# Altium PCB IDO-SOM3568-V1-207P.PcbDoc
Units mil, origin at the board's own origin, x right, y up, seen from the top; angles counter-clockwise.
Board outline 3000 x 2000 mil, 4 copper layers (TOP, VCC, GND, BOTTOM), stack 28.8 mil thick; 1 components, 686 nets, 207 pads, 0 vias.
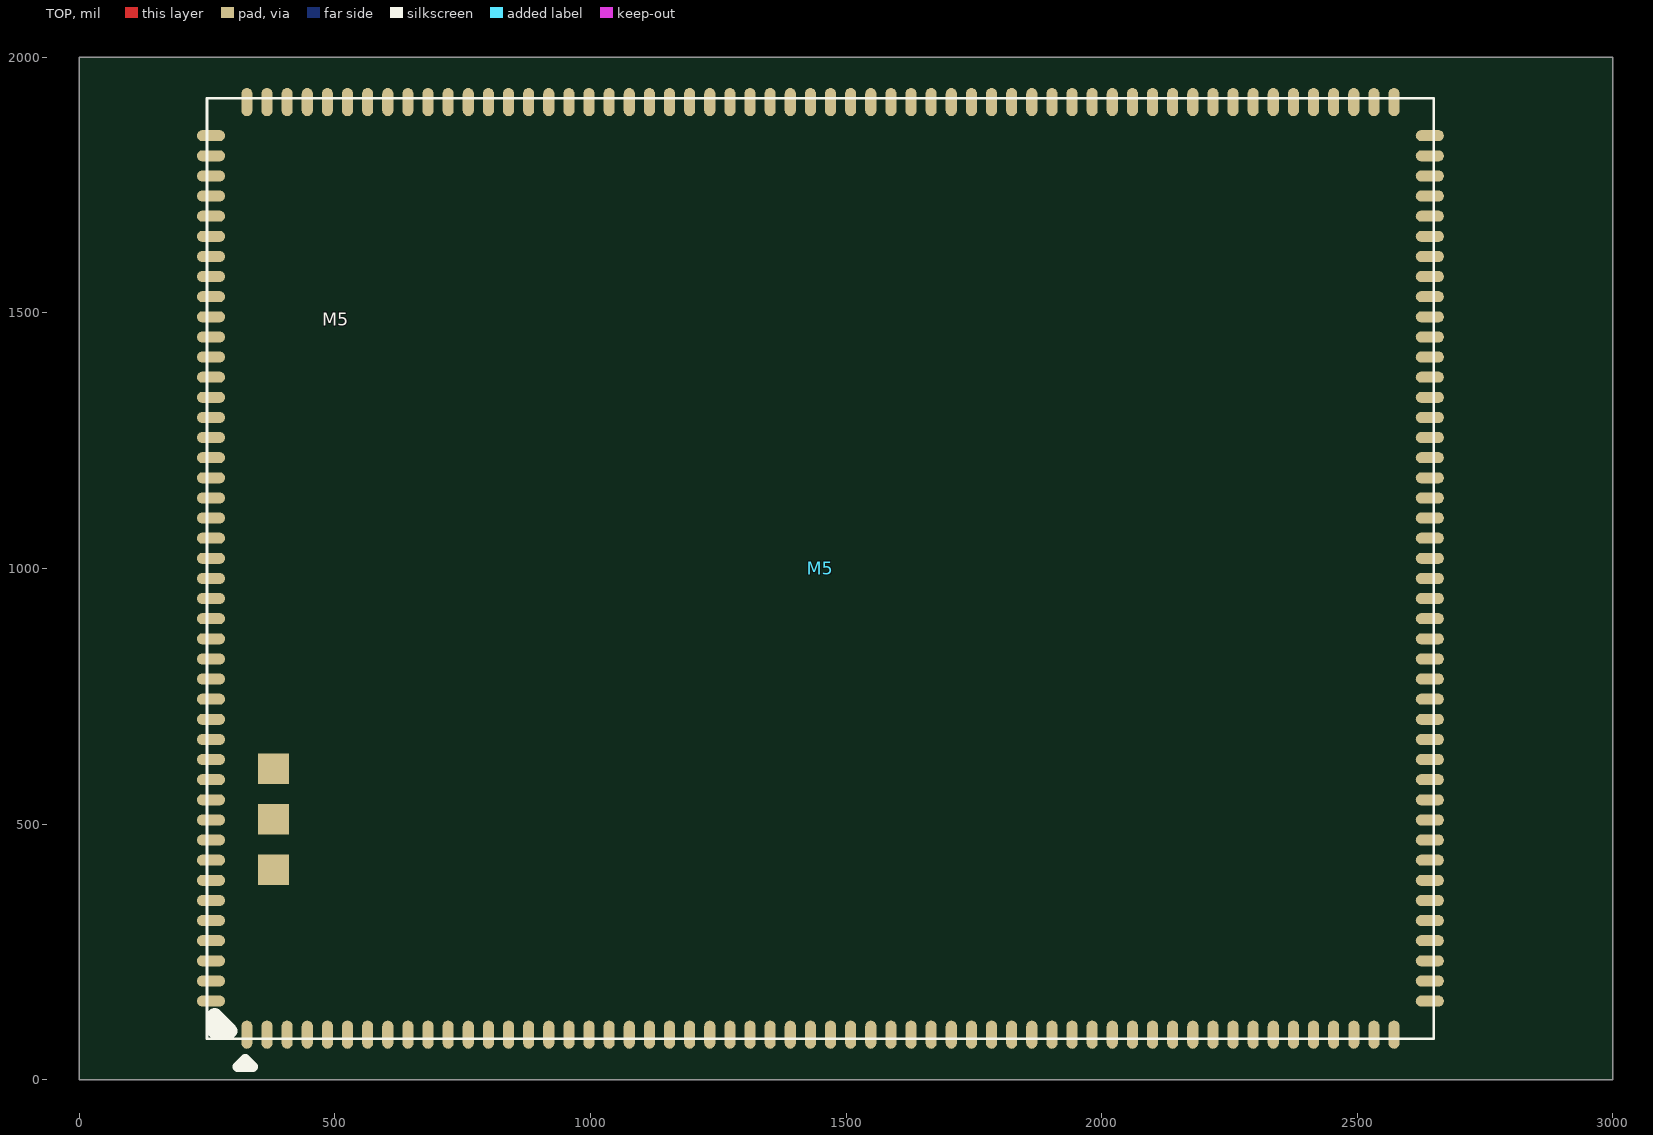
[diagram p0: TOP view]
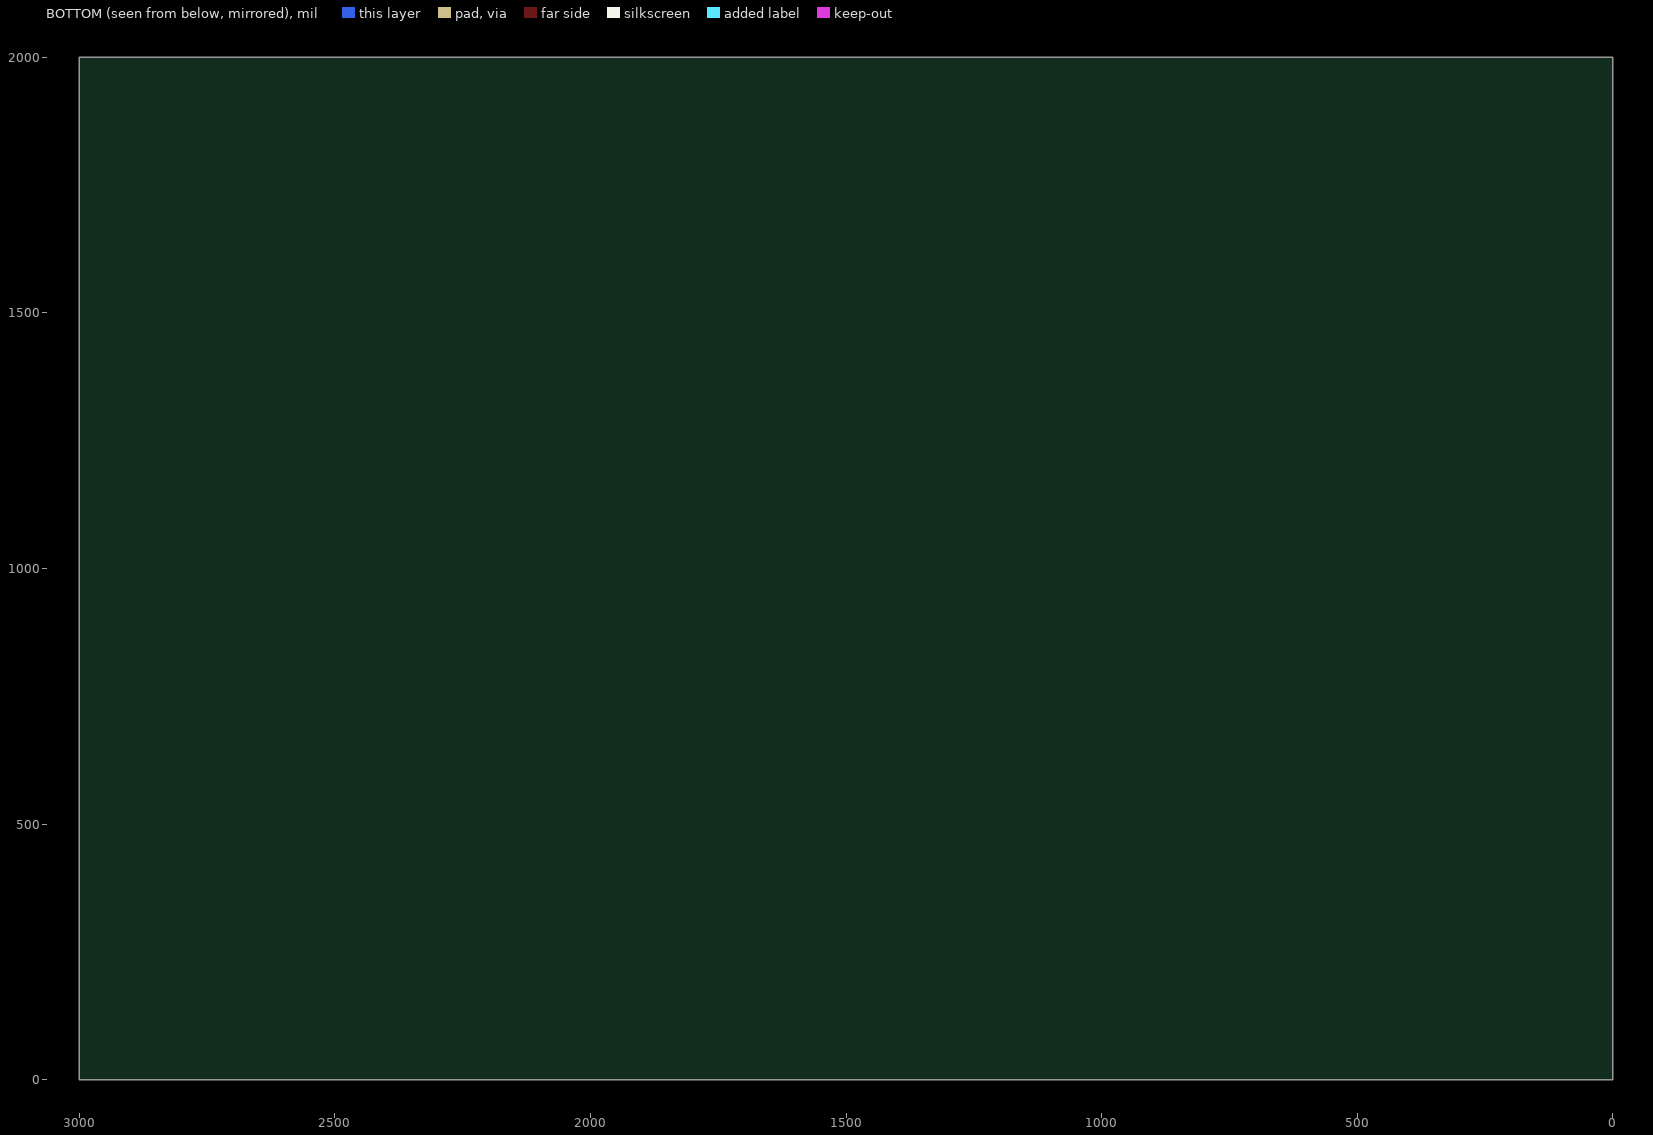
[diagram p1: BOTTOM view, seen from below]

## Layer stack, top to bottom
Top Solder: solder mask 0.4, Solder Resist, Dk 3.5
TOP: signal copper 1.2
Dielectric 1: core 8, FR-4, Dk 4.5
VCC: signal copper 1.2
Dielectric2: core 8, FR-4, Dk 4.5
GND: signal copper 1.2
Dielectric3: core 8, FR-4, Dk 4.5
BOTTOM: signal copper 1.2
Bottom Solder: solder mask 0.4, Solder Resist, Dk 3.5

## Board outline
0,2000 3000,2000 3000,0 0,0

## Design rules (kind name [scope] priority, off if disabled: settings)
Clearance [All] p1: gap=10 ignorepadtopadclearanceinfootprint=FALSE except(0: Arc-Hole Track-Hole SMDPad-Hole THPad-Hole Via-Hole Fill-Hole Poly-Hole Region-Hole Text-Hole)
DiffPairsRouting [All] p1: maxlimit=10 minlimit=10 mostfreqgap=10 toplayer_minwidth=15 toplayer_maxwidth=15 toplayer_prefwidth=15 midlayer1_minwidth=15 midlayer1_maxwidth=15 midlayer1_prefwidth=15 midlayer2_minwidth=15 midlayer2_maxwidth=15 midlayer2_prefwidth=15 bottomlayer_minwidth=15 bottomlayer_maxwidth=15 bottomlayer_prefwidth=15 maxuncoupledlength=500
PlaneConnect [All] p1: planeconnectstyle=Direct reliefexpansion=20 reliefentries=4 reliefconductorwidth=10 reliefairgap=10
PolygonConnect [All] p1: connectstyle=Direct reliefconductorwidth=10 reliefentries=4 polygonreliefangle="90 Angle" airgapwidth=10
RoutingVias [All] p1: holewidth=28 width=50 viastyle="Through Hole" minholewidth=28 minwidth=50 maxholewidth=28 maxwidth=50
SolderMaskExpansion [All] p1: expansion=4 istentingtop=FALSE
Width [All] p1: maxlimit=10 minlimit=10 preferedwidth=10 impedanceprofiledriven=TRUE minimp=0.000000 maximp=0.000000 favimp=99999999999999948800000000000000.000000
28 further rules are at their usual default settings.

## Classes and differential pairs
differential pair DIFFPAIR98: +VORN -VORP
differential pair DIFFPAIR97: +VOLN -VOLP
differential pair DIFFPAIR39: +USB3_OTG0_SSTXN_ -USB3_OTG0_SSTXP_
differential pair DIFFPAIR43: +USB3_OTG0_SSTXN -USB3_OTG0_SSTXP
differential pair DIFFPAIR48: +USB3_OTG0_SSRXN_ -USB3_OTG0_SSRXP_
differential pair DIFFPAIR49: +USB3_OTG0_SSRXN -USB3_OTG0_SSRXP
differential pair DIFFPAIR38: +USB3_OTG0_DM_ -USB3_OTG0_DP_
differential pair DIFFPAIR44: +USB3_OTG0_DM -USB3_OTG0_DP
differential pair DIFFPAIR40: +USB3_HOST1_SSTXN_ -USB3_HOST1_SSTXP_
differential pair DIFFPAIR41: +USB3_HOST1_SSTXN -USB3_HOST1_SSTXP
differential pair DIFFPAIR36: +USB3_HOST1_SSRXN_ -USB3_HOST1_SSRXP_
differential pair DIFFPAIR47: +USB3_HOST1_SSRXN -USB3_HOST1_SSRXP
differential pair DIFFPAIR37: +USB3_HOST1_DM_ -USB3_HOST1_DP_
differential pair DIFFPAIR45: +USB3_HOST1_DM -USB3_HOST1_DP
differential pair DIFFPAIR8: +USB2_HOST3_DM_ -USB2_HOST3_DP_
differential pair DIFFPAIR11: +USB2_HOST3_DM -USB2_HOST3_DP
differential pair DIFFPAIR71: +USB2_HOST2_DM -USB2_HOST2_DP
differential pair DIFFPAIR42: +SATA1_TXN -SATA1_TXP
differential pair DIFFPAIR46: +SATA1_RXN -SATA1_RXP
differential pair DIFFPAIR96: +REFCLKN_ -REFCLKP_
differential pair DIFFPAIR90: +PHY1_MDI3- -PHY1_MDI3+
differential pair DIFFPAIR89: +PHY1_MDI2- -PHY1_MDI2+
differential pair DIFFPAIR87: +PHY1_MDI1- -PHY1_MDI1+
differential pair DIFFPAIR84: +PHY1_MDI0- -PHY1_MDI0+
differential pair DIFFPAIR76: +PHY0_MDI3- -PHY0_MDI3+
differential pair DIFFPAIR77: +PHY0_MDI2- -PHY0_MDI2+
differential pair DIFFPAIR78: +PHY0_MDI1- -PHY0_MDI1+
differential pair DIFFPAIR83: +PHY0_MDI0- -PHY0_MDI0+
differential pair DIFFPAIR110: +PCIE20_TXN_ -PCIE20_TXP_
differential pair DIFFPAIR73: +PCIE20_TXN -PCIE20_TXP
differential pair DIFFPAIR109: +PCIE20_RXN_ -PCIE20_RXP_
differential pair DIFFPAIR74: +PCIE20_RXN -PCIE20_RXP
differential pair DIFFPAIR75: +PCIE20_REFCLKN -PCIE20_REFCLKP
differential pair DIFFPAIR64: +MIPI_DSI_TX1_D3N -MIPI_DSI_TX1_D3P
differential pair DIFFPAIR65: +MIPI_DSI_TX1_D2N -MIPI_DSI_TX1_D2P
differential pair DIFFPAIR67: +MIPI_DSI_TX1_D1N -MIPI_DSI_TX1_D1P
differential pair DIFFPAIR68: +MIPI_DSI_TX1_D0N -MIPI_DSI_TX1_D0P
differential pair DIFFPAIR66: +MIPI_DSI_TX1_CLKN -MIPI_DSI_TX1_CLKP
differential pair DIFFPAIR56: +MIPI_DSI_TX0_D3N_ -MIPI_DSI_TX0_D3P_
differential pair DIFFPAIR58: +MIPI_DSI_TX0_D3N -MIPI_DSI_TX0_D3P
differential pair DIFFPAIR57: +MIPI_DSI_TX0_D2N_ -MIPI_DSI_TX0_D2P_
differential pair DIFFPAIR59: +MIPI_DSI_TX0_D2N -MIPI_DSI_TX0_D2P
differential pair DIFFPAIR61: +MIPI_DSI_TX0_D1N_ -MIPI_DSI_TX0_D1P_
differential pair DIFFPAIR62: +MIPI_DSI_TX0_D1N -MIPI_DSI_TX0_D1P
differential pair DIFFPAIR69: +MIPI_DSI_TX0_D0N_ -MIPI_DSI_TX0_D0P_
differential pair DIFFPAIR70: +MIPI_DSI_TX0_D0N -MIPI_DSI_TX0_D0P
differential pair DIFFPAIR60: +MIPI_DSI_TX0_CLKN_ -MIPI_DSI_TX0_CLKP_
differential pair DIFFPAIR63: +MIPI_DSI_TX0_CLKN -MIPI_DSI_TX0_CLKP
differential pair DIFFPAIR102: +MIPI_CSI_RX_D3N -MIPI_CSI_RX_D3P
differential pair DIFFPAIR101: +MIPI_CSI_RX_D2N -MIPI_CSI_RX_D2P
differential pair DIFFPAIR100: +MIPI_CSI_RX_D1N -MIPI_CSI_RX_D1P
differential pair DIFFPAIR99: +MIPI_CSI_RX_D0N -MIPI_CSI_RX_D0P
differential pair DIFFPAIR103: +MIPI_CSI_RX_CLK0N -MIPI_CSI_RX_CLK0P
differential pair DIFFPAIR107: +MIPI_CSI_D3N -MIPI_CSI_D3P
differential pair DIFFPAIR106: +MIPI_CSI_D2N -MIPI_CSI_D2P
differential pair DIFFPAIR105: +MIPI_CSI_D1N -MIPI_CSI_D1P
differential pair DIFFPAIR104: +MIPI_CSI_D0N -MIPI_CSI_D0P
differential pair DIFFPAIR108: +MIPI_CSI_CLKN -MIPI_CSI_CLKP
differential pair DIFFPAIR25: +LVDS1_D3N -LVDS1_D3P
differential pair DIFFPAIR23: +LVDS1_D2N -LVDS1_D2P
differential pair DIFFPAIR22: +LVDS1_D1N -LVDS1_D1P
differential pair DIFFPAIR21: +LVDS1_D0N -LVDS1_D0P
differential pair DIFFPAIR24: +LVDS1_CLKN -LVDS1_CLKP
differential pair DIFFPAIR20: +LVDS0_D3N -LVDS0_D3P
differential pair DIFFPAIR18: +LVDS0_D2N -LVDS0_D2P
differential pair DIFFPAIR17: +LVDS0_D1N -LVDS0_D1P
differential pair DIFFPAIR16: +LVDS0_D0N -LVDS0_D0P
differential pair DIFFPAIR19: +LVDS0_CLKN -LVDS0_CLKP
differential pair DIFFPAIR91: +LAN1_D- -LAN1_D+
differential pair DIFFPAIR88: +LAN1_C- -LAN1_C+
differential pair DIFFPAIR86: +LAN1_B- -LAN1_B+
differential pair DIFFPAIR85: +LAN1_A- -LAN1_A+
differential pair DIFFPAIR81: +LAN0_D- -LAN0_D+
differential pair DIFFPAIR80: +LAN0_C- -LAN0_C+
differential pair DIFFPAIR79: +LAN0_B- -LAN0_B+
differential pair DIFFPAIR82: +LAN0_A- -LAN0_A+
differential pair DIFFPAIR1: +HDMI_TX_D2N_ -HDMI_TX_D2P_
differential pair DIFFPAIR0: +HDMI_TX_D2N -HDMI_TX_D2P
differential pair DIFFPAIR2: +HDMI_TX_D1N_ -HDMI_TX_D1P_
differential pair DIFFPAIR3: +HDMI_TX_D1N -HDMI_TX_D1P
differential pair DIFFPAIR4: +HDMI_TX_D0N_ -HDMI_TX_D0P_
differential pair DIFFPAIR5: +HDMI_TX_D0N -HDMI_TX_D0P
differential pair DIFFPAIR6: +HDMI_TX_CLKN_ -HDMI_TX_CLKP_
differential pair DIFFPAIR7: +HDMI_TX_CLKN -HDMI_TX_CLKP
differential pair DIFFPAIR93: +FE2.1_DM7_ -FE2.1_DP7_
differential pair DIFFPAIR92: +FE2.1_DM7 -FE2.1_DP7
differential pair DIFFPAIR52: +FE2.1_DM6_ -FE2.1_DP6_
differential pair DIFFPAIR53: +FE2.1_DM6 -FE2.1_DP6
differential pair DIFFPAIR50: +FE2.1_DM5_ -FE2.1_DP5_
differential pair DIFFPAIR51: +FE2.1_DM5 -FE2.1_DP5
differential pair DIFFPAIR54: +FE2.1_DM4_ -FE2.1_DP4_
differential pair DIFFPAIR55: +FE2.1_DM4 -FE2.1_DP4
differential pair DIFFPAIR13: +FE2.1_DM3_ -FE2.1_DP3_
differential pair DIFFPAIR15: +FE2.1_DM3 -FE2.1_DP3
differential pair DIFFPAIR12: +FE2.1_DM2_ -FE2.1_DP2_
differential pair DIFFPAIR14: +FE2.1_DM2 -FE2.1_DP2
differential pair DIFFPAIR9: +FE2.1_DM1_ -FE2.1_DP1_
differential pair DIFFPAIR10: +FE2.1_DM1 -FE2.1_DP1
differential pair DIFFPAIR72: +FE2.1_DM0 -FE2.1_DP0
differential pair DIFFPAIR27: +EDP_TX_D3N_ -EDP_TX_D3P_
differential pair DIFFPAIR26: +EDP_TX_D3N -EDP_TX_D3P
differential pair DIFFPAIR31: +EDP_TX_D2N_ -EDP_TX_D2P_
differential pair DIFFPAIR30: +EDP_TX_D2N -EDP_TX_D2P
differential pair DIFFPAIR33: +EDP_TX_D1N_ -EDP_TX_D1P_
differential pair DIFFPAIR32: +EDP_TX_D1N -EDP_TX_D1P
differential pair DIFFPAIR35: +EDP_TX_D0N_ -EDP_TX_D0P_
differential pair DIFFPAIR34: +EDP_TX_D0N -EDP_TX_D0P
differential pair DIFFPAIR29: +EDP_TX_AUXN_ -EDP_TX_AUXP_
differential pair DIFFPAIR28: +EDP_TX_AUXN -EDP_TX_AUXP

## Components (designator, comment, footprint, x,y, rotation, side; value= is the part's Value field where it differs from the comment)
M5 "MODE-204P_2_SOM3568-204P_IDO-SO" ASSEMBLY_TOP 1450,1000 r0 top

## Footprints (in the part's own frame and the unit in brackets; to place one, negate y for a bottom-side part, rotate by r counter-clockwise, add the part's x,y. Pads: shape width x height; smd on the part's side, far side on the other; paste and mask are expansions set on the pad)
ASSEMBLY_TOP [mm] "ASSEMBLY_TOP"
  oval 0.55x1.4 smd: 1(-28.499,-23.168) 2(-27.499,-23.168) 3(-26.499,-23.168) 4(-25.499,-23.168) 5(-24.499,-23.168) 6(-23.499,-23.168) 7(-22.499,-23.168) 8(-21.499,-23.168) 9(-20.499,-23.168) 10(-19.499,-23.168) 11(-18.499,-23.168) 12(-17.499,-23.168) 13(-16.499,-23.168) 14(-15.499,-23.168) 15(-14.499,-23.168) 16(-13.499,-23.168) 17(-12.499,-23.168) 18(-11.499,-23.168) 19(-10.499,-23.168) 20(-9.499,-23.168) 21(-8.499,-23.168) 22(-7.499,-23.168) 23(-6.499,-23.168) 24(-5.499,-23.168) 25(-4.499,-23.168) 26(-3.499,-23.168) 27(-2.499,-23.168) 28(-1.499,-23.168) 29(-0.499,-23.168) 30(0.501,-23.168) 31(1.501,-23.168) 32(2.501,-23.168) 33(3.501,-23.168) 34(4.501,-23.168) 35(5.501,-23.168) 36(6.501,-23.168) 37(7.501,-23.168) 38(8.501,-23.168) 39(9.501,-23.168) 40(10.501,-23.168) 41(11.501,-23.168) 42(12.501,-23.168) 43(13.501,-23.168) 44(14.501,-23.168) 45(15.501,-23.168) 46(16.501,-23.168) 47(17.501,-23.168) 48(18.501,-23.168) 49(19.501,-23.168) 50(20.501,-23.168) 51(21.501,-23.168) 52(22.501,-23.168) 53(23.501,-23.168) 54(24.501,-23.168) 55(25.501,-23.168) 56(26.501,-23.168) 57(27.501,-23.168) 58(28.501,-23.168) 103(28.501,23.168) 104(27.501,23.168) 105(26.501,23.168) 106(25.501,23.168) 107(24.501,23.168) 108(23.501,23.168) 109(22.501,23.168) 110(21.501,23.168) 111(20.501,23.168) 112(19.501,23.168) 113(18.501,23.168) 114(17.501,23.168) 115(16.501,23.168) 116(15.501,23.168) 117(14.501,23.168) 118(13.501,23.168) 119(12.501,23.168) 120(11.501,23.168) 121(10.501,23.168) 122(9.501,23.168) 123(8.501,23.168) 124(7.501,23.168) 125(6.501,23.168) 126(5.501,23.168) 127(4.501,23.168) 128(3.501,23.168) 129(2.501,23.168) 130(1.501,23.168) 131(0.501,23.168) 132(-0.499,23.168) 133(-1.499,23.168) 134(-2.499,23.168) 135(-3.499,23.168) 136(-4.499,23.168) 137(-5.499,23.168) 138(-6.499,23.168) 139(-7.499,23.168) 140(-8.499,23.168) 141(-9.499,23.168) 142(-10.499,23.168) 143(-11.499,23.168) 144(-12.499,23.168) 145(-13.499,23.168) 146(-14.499,23.168) 147(-15.499,23.168) 148(-16.499,23.168) 149(-17.499,23.168) 150(-18.499,23.168) 151(-19.499,23.168) 152(-20.499,23.168) 153(-21.499,23.168) 154(-22.499,23.168) 155(-23.499,23.168) 156(-24.499,23.168) 157(-25.499,23.168) 158(-26.499,23.168) 159(-27.499,23.168) 160(-28.499,23.168)
  oval 1.4x0.55 smd: 59(30.28,-21.499) 60(30.28,-20.499) 61(30.28,-19.499) 62(30.28,-18.499) 63(30.28,-17.499) 64(30.28,-16.499) 65(30.28,-15.499) 66(30.28,-14.499) 67(30.28,-13.499) 68(30.28,-12.499) 69(30.28,-11.499) 70(30.28,-10.499) 71(30.28,-9.499) 72(30.28,-8.499) 73(30.28,-7.499) 74(30.28,-6.499) 75(30.28,-5.499) 76(30.28,-4.499) 77(30.28,-3.499) 78(30.28,-2.499) 79(30.28,-1.499) 80(30.28,-0.499) 81(30.28,0.501) 82(30.28,1.501) 83(30.28,2.501) 84(30.28,3.501) 85(30.28,4.501) 86(30.28,5.501) 87(30.28,6.501) 88(30.28,7.501) 89(30.28,8.501) 90(30.28,9.501) 91(30.28,10.501) 92(30.28,11.501) 93(30.28,12.501) 94(30.28,13.501) 95(30.28,14.501) 96(30.28,15.501) 97(30.28,16.501) 98(30.28,17.501) 99(30.28,18.501) 100(30.28,19.501) 101(30.28,20.501) 102(30.28,21.501) 161(-30.28,21.501) 162(-30.28,20.501) 163(-30.28,19.501) 164(-30.28,18.501) 165(-30.28,17.501) 166(-30.28,16.501) 167(-30.28,15.501) 168(-30.28,14.501) 169(-30.28,13.501) 170(-30.28,12.501) 171(-30.28,11.501) 172(-30.28,10.501) 173(-30.28,9.501) 174(-30.28,8.501) 175(-30.28,7.501) 176(-30.28,6.501) 177(-30.28,5.501) 178(-30.28,4.501) 179(-30.28,3.501) 180(-30.28,2.501) 181(-30.28,1.501) 182(-30.28,0.501) 183(-30.28,-0.499) 184(-30.28,-1.499) 185(-30.28,-2.499) 186(-30.28,-3.499) 187(-30.28,-4.499) 188(-30.28,-5.499) 189(-30.28,-6.499) 190(-30.28,-7.499) 191(-30.28,-8.499) 192(-30.28,-9.499) 193(-30.28,-10.499) 194(-30.28,-11.499) 195(-30.28,-12.499) 196(-30.28,-13.499) 197(-30.28,-14.499) 198(-30.28,-15.499) 199(-30.28,-16.499) 200(-30.28,-17.499) 201(-30.28,-18.499) 202(-30.28,-19.499) 203(-30.28,-20.499) 204(-30.28,-21.499)
  rect 1.524x1.524 smd: 205(-27.178,-14.981) 206(-27.178,-12.471) 207(-27.178,-9.962)
  silkscreen extent -30.48,-24.77 30.48,23.37, body extent -31.24,-24.13 31.24,24.13, height 3.81

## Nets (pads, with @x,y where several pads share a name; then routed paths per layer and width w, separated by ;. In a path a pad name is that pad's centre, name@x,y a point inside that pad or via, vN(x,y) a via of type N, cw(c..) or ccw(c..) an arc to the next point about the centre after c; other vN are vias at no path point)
4G_5G_RESET_: 
4G_5G_RESET_GPIO3_A4: M5.123
4G_LED_WANN#: 
BT_REG_ON: 
BT_REG_ON_H_GPIO3_A7: M5.120
BT_WAKE_HOST: 
BT_WAKE_HOST_H_GPIO3_A1: M5.126
CAN1_H: 
CAN1_L: 
CAN1_RX_M0: M5.36
CAN1_RX_M0_: 
CAN1_STB_IO: 
CAN1_TX_M0: M5.37
CAN1H: 
CAN1H_: 
CAN1L: 
CAN1L_: 
CAN2_H: 
CAN2_L: 
CAN2_RX_M0: M5.75
CAN2_RX_M0_: 
CAN2_STB_IO: 
CAN2_TX_M0: M5.74
CAN2_TX_M0_: 
CAN2H: 
CAN2H_: 
CAN2L: 
CAN2L_: 
CIF_CLKO_: 
CIF_CLKOUT_SOC: M5.71
CIF_PDN0_: 
CIF_RST: 
CIF_RST_GPIO3_A3: M5.124
EDP_HPD: 
EDP_HPDIN_M1: M5.21
EDP_ON_: 
EDP_PWM4: M5.22
EDP_PWM4_: 
EDP_TX_AUXN: M5.197
EDP_TX_AUXN_: 
EDP_TX_AUXP: M5.198
EDP_TX_AUXP_: 
EDP_TX_D0N: M5.203
EDP_TX_D0N_: 
EDP_TX_D0P: M5.204
EDP_TX_D0P_: 
EDP_TX_D1N: M5.201
EDP_TX_D1N_: 
EDP_TX_D1P: M5.202
EDP_TX_D1P_: 
EDP_TX_D2N: M5.199
EDP_TX_D2N_: 
EDP_TX_D2P: M5.200
EDP_TX_D2P_: 
EDP_TX_D3N: M5.195
EDP_TX_D3N_: 
EDP_TX_D3P: M5.196
EDP_TX_D3P_: 
EXT_EN: M5.7
FE2.1_DM0: 
FE2.1_DM1: 
FE2.1_DM1_: 
FE2.1_DM2: 
FE2.1_DM2_: 
FE2.1_DM3: 
FE2.1_DM3_: 
FE2.1_DM4: 
FE2.1_DM4_: 
FE2.1_DM5: 
FE2.1_DM5_: 
FE2.1_DM6: 
FE2.1_DM6_: 
FE2.1_DM7: 
FE2.1_DM7_: 
FE2.1_DP0: 
FE2.1_DP1: 
FE2.1_DP1_: 
FE2.1_DP2: 
FE2.1_DP2_: 
FE2.1_DP3: 
FE2.1_DP3_: 
FE2.1_DP4: 
FE2.1_DP4_: 
FE2.1_DP5: 
FE2.1_DP5_: 
FE2.1_DP6: 
FE2.1_DP6_: 
FE2.1_DP7: 
FE2.1_DP7_: 
FE21_XIN: 
FE21_XOUT: 
GM_VDDIO: 
GMAC0_INT/PMEB_GPIO3_B0: M5.119
GMAC0_MCLKINOUT: M5.54
GMAC0_MDC: M5.55
GMAC0_MDIO: M5.56
GMAC0_RSTN_GPIO3_A5: M5.122
GMAC0_RXCLK: M5.41
GMAC0_RXD0: M5.50
GMAC0_RXD1: M5.51
GMAC0_RXD2: M5.39
GMAC0_RXD3: M5.40
GMAC0_RXDV_CRS: M5.52
GMAC0_TXCLK: M5.44
GMAC0_TXCLK_: 
GMAC0_TXD0: M5.47
GMAC0_TXD0_: 
GMAC0_TXD1: M5.48
GMAC0_TXD1_: 
GMAC0_TXD2: M5.42
GMAC0_TXD2_: 
GMAC0_TXD3: M5.43
GMAC0_TXD3_: 
GMAC0_TXEN: M5.49
GMAC0_TXEN_: 
GMAC1_INT/PMEB_GPIO3_C1: M5.110
GMAC1_MCLKINOUT_M1: M5.70
GMAC1_MDC_M1: M5.73
GMAC1_MDIO_M1: M5.72
GMAC1_RSTN_GPIO3_A6: M5.121
GMAC1_RXCLK_M1: M5.84
GMAC1_RXD0_M1: M5.80
GMAC1_RXD1_M1: M5.79
GMAC1_RXD2_M1: M5.86
GMAC1_RXD3_M1: M5.85
GMAC1_RXDV_CRS_M1: M5.78
GMAC1_TXCLK_M1: M5.87
GMAC1_TXCLK_M1_: 
GMAC1_TXD0_M1: M5.83
GMAC1_TXD0_M1_: 
GMAC1_TXD1_M1: M5.82
GMAC1_TXD1_M1_: 
GMAC1_TXD2_M1: M5.89
GMAC1_TXD2_M1_: 
GMAC1_TXD3_M1: M5.88
GMAC1_TXD3_M1_: 
GMAC1_TXEN_M1: M5.81
GMAC1_TXEN_M1_: 
GND: M5.4 M5.5 M5.14 M5.38 M5.98 M5.105 M5.127 M5.152 M5.179 M5.194
GND_EARTH: 
GND_IN: 
HDMI_TX_CEC_PORT: 
HDMI_TX_CLKN: M5.153
HDMI_TX_CLKN_: 
HDMI_TX_CLKP: M5.154
HDMI_TX_CLKP_: 
HDMI_TX_D0N: M5.155
HDMI_TX_D0N_: 
HDMI_TX_D0P: M5.156
HDMI_TX_D0P_: 
HDMI_TX_D1N: M5.157
HDMI_TX_D1N_: 
HDMI_TX_D1P: M5.158
HDMI_TX_D1P_: 
HDMI_TX_D2N: M5.159
HDMI_TX_D2N_: 
HDMI_TX_D2P: M5.160
HDMI_TX_D2P_: 
HDMI_TX_HPD_PORT: 
HDMI_TX_HPDIN: M5.148
HDMI_TXDDC_SCL_PORT: 
HDMI_TXDDC_SDA_PORT: 
HDMITX_CEC_M0: M5.151
HOST_WAKE_BT: 
HOST_WAKE_BT_H_GPIO3_A2: M5.125
HP_DET_H_GPIO0_C5: M5.24
HP_SNS: M5.10
HPL_OUT: M5.9
HPR_OUT: M5.11
HUB_RST_: 
I2C1_SCL: M5.32
I2C1_SCL_RTC: 
I2C1_SDA: M5.33
I2C1_SDA_RTC: 
I2C2_SCL_M0: M5.34
I2C2_SDA_M0: M5.35
I2C3_SCL_M1: M5.114
I2C3_SDA_M1: M5.113
I2C4_SCL_M0: M5.76
I2C4_SDA_M0: M5.77
I2C5_SCL-HDMI: M5.150
I2C5_SDA-HDMI: M5.149
LAN0_A+: 
LAN0_A-: 
LAN0_B+: 
LAN0_B-: 
LAN0_C+: 
LAN0_C-: 
LAN0_D+: 
LAN0_D-: 
LAN1_A+: 
LAN1_A-: 
LAN1_B+: 
LAN1_B-: 
LAN1_C+: 
LAN1_C-: 
LAN1_D+: 
LAN1_D-: 
LCM_VIO_EN: 
LVDS0_CLKN: 
LVDS0_CLKP: 
LVDS0_D0N: 
LVDS0_D0P: 
LVDS0_D1N: 
LVDS0_D1P: 
LVDS0_D2N: 
LVDS0_D2P: 
LVDS0_D3N: 
LVDS0_D3P: 
LVDS1_CLKN: 
LVDS1_CLKP: 
LVDS1_D0N: 
LVDS1_D0P: 
LVDS1_D1N: 
LVDS1_D1P: 
LVDS1_D2N: 
LVDS1_D2P: 
LVDS1_D3N: 
LVDS1_D3P: 
LVDS_ON_: 
LVDS_PWM5: M5.23
LVDS_PWM5_: 
LVDS_VIO: 
LVDS_VIO_: 
MIC1_INN: M5.13
MIC1_INP: M5.12
MIPI_CAM0_PDN_L_GPIO2_C1: M5.53
MIPI_CSI_CLKN: 
MIPI_CSI_CLKP: 
MIPI_CSI_D0N: 
MIPI_CSI_D0P: 
MIPI_CSI_D1N: 
MIPI_CSI_D1P: 
MIPI_CSI_D2N: 
MIPI_CSI_D2P: 
MIPI_CSI_D3N: 
MIPI_CSI_D3P: 
MIPI_CSI_RX_CLK0N: M5.170
MIPI_CSI_RX_CLK0P: M5.169
MIPI_CSI_RX_CLK1N: M5.172
MIPI_CSI_RX_CLK1P: M5.171
MIPI_CSI_RX_D0N: M5.162
MIPI_CSI_RX_D0P: M5.161
MIPI_CSI_RX_D1N: M5.164
MIPI_CSI_RX_D1P: M5.163
MIPI_CSI_RX_D2N: M5.166
MIPI_CSI_RX_D2P: M5.165
MIPI_CSI_RX_D3N: M5.168
MIPI_CSI_RX_D3P: M5.167
MIPI_DSI_TX0_CLKN: M5.142
MIPI_DSI_TX0_CLKN_: 
MIPI_DSI_TX0_CLKP: M5.143
MIPI_DSI_TX0_CLKP_: 
MIPI_DSI_TX0_D0N: M5.146
MIPI_DSI_TX0_D0N_: 
MIPI_DSI_TX0_D0P: M5.147
MIPI_DSI_TX0_D0P_: 
MIPI_DSI_TX0_D1N: M5.144
MIPI_DSI_TX0_D1N_: 
MIPI_DSI_TX0_D1P: M5.145
MIPI_DSI_TX0_D1P_: 
MIPI_DSI_TX0_D2N: M5.140
MIPI_DSI_TX0_D2N_: 
MIPI_DSI_TX0_D2P: M5.141
MIPI_DSI_TX0_D2P_: 
MIPI_DSI_TX0_D3N: M5.138
MIPI_DSI_TX0_D3N_: 
MIPI_DSI_TX0_D3P: M5.139
MIPI_DSI_TX0_D3P_: 
MIPI_DSI_TX0_RST: 
MIPI_DSI_TX1_CLKN: M5.132
MIPI_DSI_TX1_CLKP: M5.133
MIPI_DSI_TX1_D0N: M5.136
MIPI_DSI_TX1_D0P: M5.137
MIPI_DSI_TX1_D1N: M5.134
MIPI_DSI_TX1_D1P: M5.135
MIPI_DSI_TX1_D2N: M5.130
MIPI_DSI_TX1_D2P: M5.131
MIPI_DSI_TX1_D3N: M5.128
MIPI_DSI_TX1_D3P: M5.129
MIPI_DSI_TX1_RST: 
MIPI_TX0_BL_PWM5: 
MIPI_TX1_BL_PWM4: 
MPU6500_AD0: 
N17052705: 
N17052995: 
N17053074: 
N17053234: 
N17053342: 
N17053374: 
N17053434: 
N17846666: 
N67123537: 
N67146313: 
N67159131: 
N67228394: 
N67228398: 
N67228404: 
N67269040: 
N67928236: 
N67928238: 
N67928242: 
N67928244: 
N67928270: 
N67928274: 
N68112138: 
N68117516: 
N68117520: 
N68117689: 
N68120764: 
N68141872: 
N68149060: 
N68226715: 
N68226717: 
N68226719: 
N68226721: 
N68234263: 
N68234265: 
N68234885: 
N68235937: 
N68290667: 
N68290669: 
N68290717: 
N68290719: 
N68290721: 
N68290723: 
N68290736: 
N68290738: 
N68290823: 
N68391184: 
N68391237: 
N68391239: 
N68444772: 
N68540703: 
N68550545: 
N68551303: 
N68551306: 
N68551396: 
N68552374: 
N68552446: 
N68558276: 
N68558638: 
N68563618: 
N68563661: 
N68582360: 
N68582430: 
N68600227: 
N68600229: 
N68600231: 
N68600309: 
N68610828: 
N68611164: 
N68644173: 
N68693421: 
N68696061: 
N68696295: 
N68706836: 
N68707388: 
N68721096: 
N68721887: 
N68721931: 
N68721933: 
N68723170: 
N68753609: 
N68753612: 
N68753720: 
N68753740: 
N68754791: 
N68764417: 
N68764421: 
N68764430: 
N68782340: 
N68782427: 
N68782451: 
N68784083: 
N68821934: 
N68821936: 
N68825811: 
N68865571: 
N68866830: 
N68869057: 
N68869059: 
N68869063: 
N68869065: 
N68869069: 
N68869073: 
N68869089: 
N68869091: 
N68869093: 
N68869095: 
N68871128: 
N68871171: 
N68877118: 
N68877190: 
N68886075: 
N68888039: 
N69126369: 
N69153757: 
N69164567: 
N69167857: 
N69206132: 
N69206262: 
N69206971: 
NSD_CD: 
PCA9539_A0: 
PCA9539_A1: 
PCA9539_I2C_SCL: 
PCA9539_I2C_SDA: 
PCA9539_INT: 
PCA9539_INT_GPIO4_C4: M5.29
PCA9539_IO0_0: 
PCA9539_IO0_1: 
PCA9539_IO0_2: 
PCA9539_IO0_3: 
PCA9539_IO0_4: 
PCA9539_IO0_5: 
PCA9539_IO0_6: 
PCA9539_IO0_7: 
PCA9539_IO1_0: 
PCA9539_IO1_1: 
PCA9539_IO1_3: 
PCA9539_IO1_4: 
PCA9539_IO1_5: 
PCA9539_IO1_6: 
PCA9539_IO1_7: 
PCA9539_RST: 
PCIE20_REFCLKN: M5.178
PCIE20_REFCLKP: M5.177
PCIE20_RXN: M5.176
PCIE20_RXN_: 
PCIE20_RXP: M5.175
PCIE20_RXP_: 
PCIE20_TXN: M5.174
PCIE20_TXN_: 
PCIE20_TXP: M5.173
PCIE20_TXP_: 
PHY0_CLKOUT125: 
PHY0_G_LED-: 
PHY0_LED0/CFG_EXT: 
PHY0_LED1/CFG_LDO0: 
PHY0_LED2/CFG_LDO1: 
PHY0_MDI0+: 
PHY0_MDI0-: 
PHY0_MDI1+: 
PHY0_MDI1-: 
PHY0_MDI2+: 
PHY0_MDI2-: 
PHY0_MDI3+: 
PHY0_MDI3-: 
PHY0_REG_OUT: 
PHY0_RSTN: 
PHY0_RXCLK/PHYAD1: 
PHY0_RXD0/RXDLY: 
PHY0_RXD1/TXDLY: 
PHY0_RXD2/PLLOFF: 
PHY0_RXD3/PHYAD0: 
PHY0_RXDV/PHYAD2: 
PHY0_XTALIN: 
PHY0_XTALOUT: 
PHY0_Y_LED+: 
PHY1_CLKOUT125: 
PHY1_G_LED-: 
PHY1_LED0/CFG_EXT: 
PHY1_LED1/CFG_LDO0: 
PHY1_LED2/CFG_LDO1: 
PHY1_MDI0+: 
PHY1_MDI0-: 
PHY1_MDI1+: 
PHY1_MDI1-: 
PHY1_MDI2+: 
PHY1_MDI2-: 
PHY1_MDI3+: 
PHY1_MDI3-: 
PHY1_REG_OUT: 
PHY1_RSTN: 
PHY1_RXCLK/PHYAD1: 
PHY1_RXD0/RXDLY: 
PHY1_RXD1/TXDLY: 
PHY1_RXD2/PLLOFF: 
PHY1_RXD3/PHYAD0: 
PHY1_RXDV/PHYAD2: 
PHY1_XTALIN: 
PHY1_XTALOUT: 
PHY1_Y_LED+: 
PWM7_IR: M5.25
REFCLK_GM8775C: 
REFCLKN_: 
REFCLKP_: 
REXT: 
RK809_PWRON: M5.8
RK809_VDC: M5.6
RS485_5_DM: 
RS485_5_DP: 
RS485_5_RW_EN: 
RS485_7_DM: 
RS485_7_DP: 
RS485_7_RW_EN: 
RSET0: 
RSET1: 
RTCIC_32KOUT: 
S0RX: 
S0RX_: 
S0TX: 
S0TX_: 
S3RX_M1: 
S3RX_M1_: 
S3TX_M1: 
S3TX_M1_: 
S4RX_M1: 
S4RX_M1_: 
S4TX_M1: 
S4TX_M1_: 
S5RX_M1: 
S5RX_M1/RS485-A5: 
S5RX_M1_: 
S5TX_M1: 
S5TX_M1/RS485-B5: 
S5TX_M1_: 
S7RX_M1: 
S7RX_M1/RS485-A7: 
S7RX_M1_: 
S7TX_M1: 
S7TX_M1/RS485-B7: 
S7TX_M1_: 
SARADC_VIN0_KEY/RECOVERY: M5.15
SARADC_VIN2_HP_HOOK: M5.16
SARADC_VIN4: M5.17
SARADC_VIN5: M5.18
SATA1_RXN: 
SATA1_RXP: 
SATA1_TXN: 
SATA1_TXP: 
SCL_CAM: 
SD_CLK: 
SD_CMD: 
SD_D0: 
SD_D1: 
SD_D2: 
SD_D3: 
SDA_CAM: 
SDMMC0_CLK: M5.63
SDMMC0_CMD: M5.64
SDMMC0_D0: M5.68
SDMMC0_D1: M5.67
SDMMC0_D2: M5.66
SDMMC0_D3: M5.65
SDMMC0_DET_L: M5.62
SDMMC2_CLK_M0: M5.92
SDMMC2_CMD_M0: M5.93
SDMMC2_D0_M0: M5.97
SDMMC2_D1_M0: M5.96
SDMMC2_D2_M0: M5.95
SDMMC2_D3_M0: M5.94
SIM_CLK: 
SIM_DATA: 
SIM_DET: 
SIM_RST: 
SPI3_CLK_M1: M5.27
SPI3_CS0_M1: M5.31
SPI3_MISO_M1: M5.30
SPI3_MOSI_M1: M5.28
SPK_5V: 
SPK_CTL_H_: 
SPK_MUTE_H_: 
SYS_LED_GPIO0_C7: M5.26
TP_INT: 
TP_INT_L_GPIO3_B4: M5.115
TP_RST: 
TP_RST_L_GPIO3_B3: M5.116
TP_SCL: 
TP_SDA: 
UART0_RX: M5.19
UART0_RX_: 
UART0_TX: M5.20
UART2_RX_M0: M5.60
UART2_TX_M0: M5.59
UART3_RX_M1: M5.111
UART3_RX_M1_: 
UART3_TX_M1: M5.112
UART4_RX_M1: M5.118
UART4_RX_M1_: 
UART4_TX_M1: M5.117
UART5_RX_M1: M5.108
UART5_RX_M1_: 
UART5_TX_M1: M5.109
UART7_RX_M1: M5.106
UART7_TX_M1: M5.107
UART8_CTSN_M0: M5.46
UART8_RTSN_M0: M5.45
UART8_RX_M0: M5.58
UART8_TX_M0: M5.57
USB2_HOST2_DM: M5.99
USB2_HOST2_DP: M5.100
USB2_HOST3_DM: M5.101
USB2_HOST3_DM_: 
USB2_HOST3_DP: M5.102
USB2_HOST3_DP_: 
USB3_HOST1_DM: M5.182
USB3_HOST1_DM_: 
USB3_HOST1_DP: M5.183
USB3_HOST1_DP_: 
USB3_HOST1_SSRXN: M5.185
USB3_HOST1_SSRXN_: 
USB3_HOST1_SSRXP: M5.184
USB3_HOST1_SSRXP_: 
USB3_HOST1_SSTXN: M5.181
USB3_HOST1_SSTXN_: 
USB3_HOST1_SSTXP: M5.180
USB3_HOST1_SSTXP_: 
USB3_OTG0_DM: M5.188
USB3_OTG0_DM_: 
USB3_OTG0_DP: M5.189
USB3_OTG0_DP_: 
USB3_OTG0_ID: M5.193
USB3_OTG0_SSRXN: M5.191
USB3_OTG0_SSRXN_: 
USB3_OTG0_SSRXP: M5.190
USB3_OTG0_SSRXP_: 
USB3_OTG0_SSTXN: M5.187
USB3_OTG0_SSTXN_: 
USB3_OTG0_SSTXP: M5.186
USB3_OTG0_SSTXP_: 
USB3_OTG0_VBUSDET: M5.192
USB_OTG_PWREN_H: M5.61
VBAT_RTC: 
VBAT_WL_1T1R: 
VBUSM: 
VCC1V5_DVP: 
VCC1V8_DVP: 
VCC2V8_DVP: 
VCC3V3_PHY0: 
VCC3V3_PHY1: 
VCC3V3_SD: M5.69
VCC5V0_SYS: M5.1 M5.2 M5.3
VCC5V0_USB_FE_D1: 
VCC5V0_USB_FE_D2: 
VCC5V0_USB_FE_D3: 
VCC5V0_USB_FE_D4: 
VCC5V0_USB_FE_D5: 
VCC5V0_USB_FE_D6: 
VCC5V0_USB_HOST1: 
VCC5V0_USB_HOST3: 
VCC5V0_USB_OTG0: 
VCC5V_HDMI_TX: 
VCC12V_DC_IN: 
VCC12V_DCIN: 
VCC_1V8: M5.103
VCC_1V8_HUB: 
VCC_3V3: M5.104
VCC_3V3_HUB: 
VCC_3V8: 
VCC_5V_HUB: 
VCC_485: 
VCC_EDP_OUT: 
VCC_EDP_OUT_: 
VCC_LEDA_TX0: 
VCC_LEDA_TX1: 
VCC_LEDK_TX0: 
VCC_LEDK_TX1: 
VCC_SIM: 
VCCA_CODEC: 
VCCIO_ACODEC: 
VCCIO_PHY0: 
VCCIO_PHY1: 
VCCIO_WL: 
VDD10_PHY0: 
VDD10_PHY1: 
VDD_3V3: 
VDD_LVDS: 
VDD_RTC: 
VDD_USB_5V: 
VOLN: 
VOLP: 
VORN: 
VORP: 
WIFI1T1R_CLK: 
WIFI1T1R_CMD: 
WIFI1T1R_D0: 
WIFI1T1R_D1: 
WIFI1T1R_D2: 
WIFI1T1R_D3: 
WIFI1T1R_XTAL_IN: 
WIFI1T1R_XTAL_OUT: 
WIFI_REG_ON_H_GPIO3_D4: M5.91
WIFI_WAKE_HOST_H_GPIO3_D5: M5.90
WIFIBT_32KIN_1T1R: 
pads on no net: M5.205 M5.206 M5.207

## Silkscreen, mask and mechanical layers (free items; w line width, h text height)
OUTLINE:
  the board outline again, w1
DRAWING_ORIGIN:
  lines w1: -25,0 25,0 ; 0,-25 0,25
